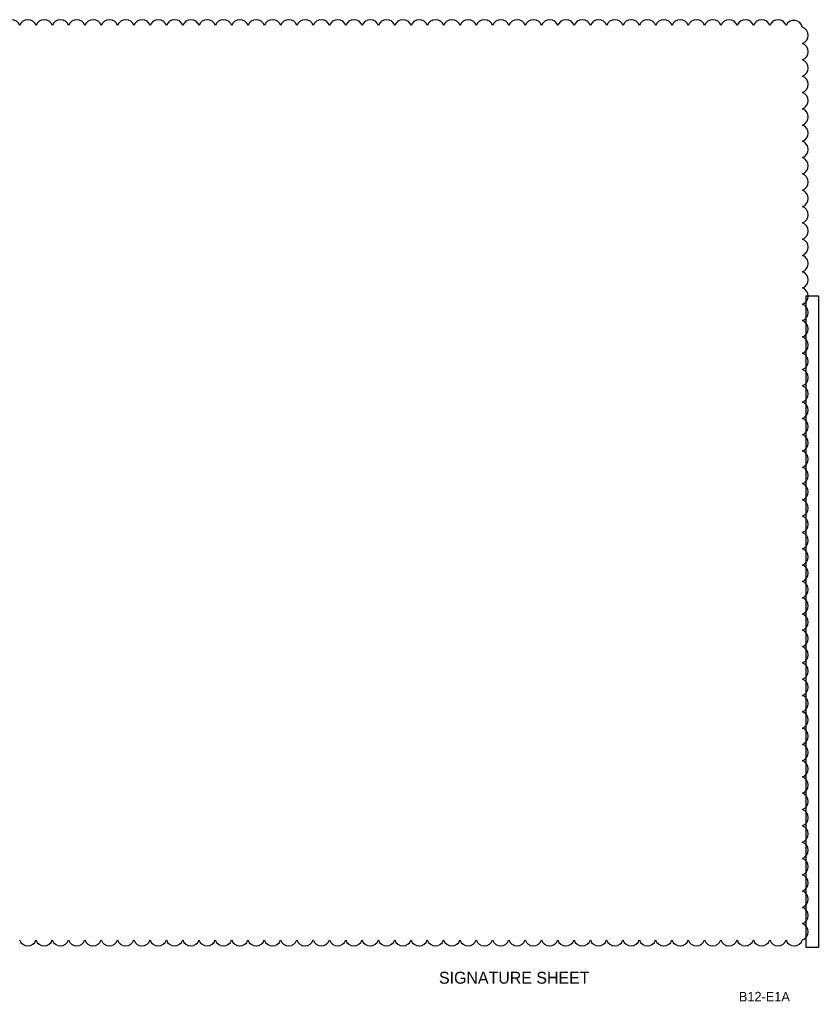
# Model space of a CAD drawing. Extents: x -811.3 to -795.2, y -2199.5 to -2188.9.
# Drawn here: x -803.6 to -795.22, y -2199.25 to -2188.94 of the extents above; entities that cross this region are included whole.
import ezdxf

# ---------------------------------------------------------------- set-up
doc = ezdxf.new("R2010")
doc.units = 0
for name, color, linetype in [('AdhocPoint_dp', 7, 'Continuous'), ('ScratchEle_dp', 7, 'Continuous'), ('SheetBorder_dp', 7, 'Continuous'), ('TextMisc', 7, 'Continuous')]:
    doc.layers.add(name, color=color, linetype=linetype)

msp = doc.modelspace()

# ---------------------------------------------------------------- linework, layer by layer
at = {"layer": 'ScratchEle_dp'}
for centre, radius, start, end in [((-803.684, -2189.028), 0.0897, 17.5, 162.5), ((-803.513, -2189.028), 0.0897, 17.5, 162.5), ((-803.342, -2189.028), 0.0897, 17.5, 162.5), ((-803.171, -2189.028), 0.0897, 17.5, 162.5), ((-803, -2189.028), 0.0897, 17.5, 162.5), ((-802.829, -2189.028), 0.0897, 17.5, 162.5), ((-802.657, -2189.028), 0.0897, 17.5, 162.5), ((-802.486, -2189.028), 0.0897, 17.5, 162.5), ((-802.315, -2189.028), 0.0897, 17.5, 162.5), ((-802.144, -2189.028), 0.0897, 17.5, 162.5), ((-801.973, -2189.028), 0.0897, 17.5, 162.5), ((-801.802, -2189.028), 0.0897, 17.5, 162.5), ((-801.631, -2189.028), 0.0897, 17.5, 162.5), ((-801.46, -2189.028), 0.0897, 17.5, 162.5), ((-801.288, -2189.028), 0.0897, 17.5, 162.5), ((-801.117, -2189.028), 0.0897, 17.5, 162.5), ((-800.946, -2189.028), 0.0897, 17.5, 162.5), ((-800.775, -2189.028), 0.0897, 17.5, 162.5), ((-800.604, -2189.028), 0.0897, 17.5, 162.5), ((-800.433, -2189.028), 0.0897, 17.5, 162.5), ((-800.262, -2189.028), 0.0897, 17.5, 162.5), ((-800.091, -2189.028), 0.0897, 17.5, 162.5), ((-799.919, -2189.028), 0.0897, 17.5, 162.5), ((-799.748, -2189.028), 0.0897, 17.5, 162.5), ((-799.577, -2189.028), 0.0897, 17.5, 162.5), ((-799.406, -2189.028), 0.0897, 17.5, 162.5), ((-799.235, -2189.028), 0.0897, 17.5, 162.5), ((-799.064, -2189.028), 0.0897, 17.5, 162.5), ((-798.893, -2189.028), 0.0897, 17.5, 162.5), ((-798.722, -2189.028), 0.0897, 17.5, 162.5), ((-798.551, -2189.028), 0.0897, 17.5, 162.5), ((-798.379, -2189.028), 0.0897, 17.5, 162.5), ((-798.208, -2189.028), 0.0897, 17.5, 162.5), ((-798.037, -2189.028), 0.0897, 17.5, 162.5), ((-797.866, -2189.028), 0.0897, 17.5, 162.5), ((-797.695, -2189.028), 0.0897, 17.5, 162.5), ((-797.524, -2189.028), 0.0897, 17.5, 162.5), ((-797.353, -2189.028), 0.0897, 17.5, 162.5), ((-797.182, -2189.028), 0.0897, 17.5, 162.5), ((-797.01, -2189.028), 0.0897, 17.5, 162.5), ((-796.839, -2189.028), 0.0897, 17.5, 162.5), ((-796.668, -2189.028), 0.0897, 17.5, 162.5), ((-796.497, -2189.028), 0.0897, 17.5, 162.5), ((-796.326, -2189.028), 0.0897, 17.5, 162.5), ((-796.155, -2189.028), 0.0897, 17.5, 162.5), ((-795.984, -2189.028), 0.0897, 17.5, 162.5), ((-795.813, -2189.028), 0.0897, 17.5, 162.5), ((-795.641, -2189.028), 0.0897, 17.5, 162.5), ((-795.474, -2189.036), 0.0896, 11.7454, 156.7454), ((-795.413, -2189.103), 0.0897, 287.5, 72.5), ((-795.413, -2189.274), 0.0897, 287.5, 72.5), ((-795.413, -2189.446), 0.0897, 287.5, 72.5), ((-795.413, -2189.617), 0.0897, 287.5, 72.5), ((-795.413, -2189.788), 0.0897, 287.5, 72.5), ((-795.413, -2189.959), 0.0897, 287.5, 72.5), ((-795.413, -2190.13), 0.0897, 287.5, 72.5), ((-795.413, -2190.301), 0.0897, 287.5, 72.5), ((-795.413, -2190.472), 0.0897, 287.5, 72.5), ((-795.413, -2190.643), 0.0897, 287.5, 72.5), ((-795.413, -2190.815), 0.0897, 287.5, 72.5), ((-795.413, -2190.986), 0.0897, 287.5, 72.5), ((-795.413, -2191.157), 0.0897, 287.5, 72.5), ((-795.413, -2191.328), 0.0897, 287.5, 72.5), ((-795.413, -2191.499), 0.0897, 287.5, 72.5), ((-795.413, -2191.67), 0.0897, 287.5, 72.5), ((-795.413, -2191.841), 0.0897, 287.5, 72.5), ((-795.413, -2192.012), 0.0897, 287.5, 72.5), ((-795.413, -2192.184), 0.0897, 287.5, 72.5), ((-795.413, -2192.355), 0.0897, 287.5, 72.5), ((-795.413, -2192.526), 0.0897, 287.5, 72.5), ((-795.413, -2192.697), 0.0897, 287.5, 72.5), ((-795.413, -2192.868), 0.0897, 287.5, 72.5), ((-795.413, -2193.039), 0.0897, 287.5, 72.5), ((-795.413, -2193.21), 0.0897, 287.5, 72.5), ((-795.413, -2193.381), 0.0897, 287.5, 72.5), ((-795.413, -2193.553), 0.0897, 287.5, 72.5), ((-795.413, -2193.724), 0.0897, 287.5, 72.5), ((-795.413, -2193.895), 0.0897, 287.5, 72.5), ((-795.413, -2194.066), 0.0897, 287.5, 72.5), ((-795.413, -2194.237), 0.0897, 287.5, 72.5), ((-795.413, -2194.408), 0.0897, 287.5, 72.5), ((-795.413, -2194.579), 0.0897, 287.5, 72.5), ((-795.413, -2194.75), 0.0897, 287.5, 72.5), ((-795.413, -2194.922), 0.0897, 287.5, 72.5), ((-795.413, -2195.093), 0.0897, 287.5, 72.5), ((-795.413, -2195.264), 0.0897, 287.5, 72.5), ((-795.413, -2195.435), 0.0897, 287.5, 72.5), ((-795.413, -2195.606), 0.0897, 287.5, 72.5), ((-795.413, -2195.777), 0.0897, 287.5, 72.5), ((-795.413, -2195.948), 0.0897, 287.5, 72.5), ((-795.413, -2196.119), 0.0897, 287.5, 72.5), ((-795.413, -2196.29), 0.0897, 287.5, 72.5), ((-795.413, -2196.462), 0.0897, 287.5, 72.5), ((-795.413, -2196.633), 0.0897, 287.5, 72.5), ((-795.413, -2196.804), 0.0897, 287.5, 72.5), ((-795.413, -2196.975), 0.0897, 287.5, 72.5), ((-795.413, -2197.146), 0.0897, 287.5, 72.5), ((-795.413, -2197.317), 0.0897, 287.5, 72.5), ((-795.413, -2197.488), 0.0897, 287.5, 72.5), ((-795.413, -2197.659), 0.0897, 287.5, 72.5), ((-795.413, -2197.831), 0.0897, 287.5, 72.5), ((-795.413, -2198.002), 0.0897, 287.5, 72.5), ((-795.413, -2198.173), 0.0897, 287.5, 72.5), ((-795.413, -2198.344), 0.0897, 287.5, 72.5), ((-795.413, -2198.515), 0.0897, 287.5, 72.5), ((-803.514, -2198.574), 0.0897, 197.5, 342.5), ((-803.343, -2198.574), 0.0897, 197.5, 342.5), ((-803.172, -2198.574), 0.0897, 197.5, 342.5), ((-803.001, -2198.574), 0.0897, 197.5, 342.5), ((-802.83, -2198.574), 0.0897, 197.5, 342.5), ((-802.658, -2198.574), 0.0897, 197.5, 342.5), ((-802.487, -2198.574), 0.0897, 197.5, 342.5), ((-802.316, -2198.574), 0.0897, 197.5, 342.5), ((-802.145, -2198.574), 0.0897, 197.5, 342.5), ((-801.974, -2198.574), 0.0897, 197.5, 342.5), ((-801.803, -2198.574), 0.0897, 197.5, 342.5), ((-801.632, -2198.574), 0.0897, 197.5, 342.5), ((-801.461, -2198.574), 0.0897, 197.5, 342.5), ((-801.289, -2198.574), 0.0897, 197.5, 342.5), ((-801.118, -2198.574), 0.0897, 197.5, 342.5), ((-800.947, -2198.574), 0.0897, 197.5, 342.5), ((-800.776, -2198.574), 0.0897, 197.5, 342.5), ((-800.605, -2198.574), 0.0897, 197.5, 342.5), ((-800.434, -2198.574), 0.0897, 197.5, 342.5), ((-800.263, -2198.574), 0.0897, 197.5, 342.5), ((-800.092, -2198.574), 0.0897, 197.5, 342.5), ((-799.921, -2198.574), 0.0897, 197.5, 342.5), ((-799.749, -2198.574), 0.0897, 197.5, 342.5), ((-799.578, -2198.574), 0.0897, 197.5, 342.5), ((-799.407, -2198.574), 0.0897, 197.5, 342.5), ((-799.236, -2198.574), 0.0897, 197.5, 342.5), ((-799.065, -2198.574), 0.0897, 197.5, 342.5), ((-798.894, -2198.574), 0.0897, 197.5, 342.5), ((-798.723, -2198.574), 0.0897, 197.5, 342.5), ((-798.552, -2198.574), 0.0897, 197.5, 342.5), ((-798.38, -2198.574), 0.0897, 197.5, 342.5), ((-798.209, -2198.574), 0.0897, 197.5, 342.5), ((-798.038, -2198.574), 0.0897, 197.5, 342.5), ((-797.867, -2198.574), 0.0897, 197.5, 342.5), ((-797.696, -2198.574), 0.0897, 197.5, 342.5), ((-797.525, -2198.574), 0.0897, 197.5, 342.5), ((-797.354, -2198.574), 0.0897, 197.5, 342.5), ((-797.183, -2198.574), 0.0897, 197.5, 342.5), ((-797.011, -2198.574), 0.0897, 197.5, 342.5), ((-796.84, -2198.574), 0.0897, 197.5, 342.5), ((-796.669, -2198.574), 0.0897, 197.5, 342.5), ((-796.498, -2198.574), 0.0897, 197.5, 342.5), ((-796.327, -2198.574), 0.0897, 197.5, 342.5), ((-796.156, -2198.574), 0.0897, 197.5, 342.5), ((-795.985, -2198.574), 0.0897, 197.5, 342.5), ((-795.814, -2198.574), 0.0897, 197.5, 342.5), ((-795.642, -2198.574), 0.0897, 197.5, 342.5), ((-795.471, -2198.574), 0.0897, 197.5, 342.5)]:
    msp.add_arc(centre, radius, start, end, dxfattribs=at)
at = {"layer": 'TextMisc'}
msp.add_lwpolyline([(-795.346, -2191.838), (-795.218, -2191.838), (-795.218, -2198.68), (-795.346, -2198.68)], close=True, dxfattribs=at)

# ---------------------------------------------------------------- texts
at = {"layer": 'AdhocPoint_dp'}
msp.add_text('B12-E1A', height=0.1, dxfattribs=at).set_placement((-796.052, -2199.246))
at = {"layer": 'SheetBorder_dp'}
msp.add_text('       SIGNATURE SHEET         ', height=0.125, dxfattribs=at).set_placement((-799.524, -2199.06))

doc.saveas('drawing.dxf')
